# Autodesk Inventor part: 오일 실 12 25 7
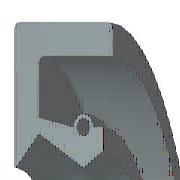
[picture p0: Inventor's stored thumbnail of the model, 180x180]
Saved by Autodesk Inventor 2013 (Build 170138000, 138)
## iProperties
IsCustomPart: 1
Created: 2012-02
Part Number: 오일 실 12 25 7
Material: 고무
Description: 오일-실
Document SubType Name: Modeling
Standard: KS B 2804
Designer: test
Standards Organization: KS
Language: ko-KR
Size Designation: D - 12 25 7
Categories: <MemberInstance><Categories><Category DisplayName="샤프트 부품" InternalName="7f7aeb1f-a693-4053-b835-cee3144e0d98" Mnemonic="SHFT"><Category DisplayName="실링" Intern
Density: 0.93 g/cm^3
Author: test
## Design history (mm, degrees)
revolve "본체" stored, may be unused: angle "d17" = 90 deg
revolve "스프링1" stored, may be unused: angle "d18" = 90 deg
body "Solid1"
sketch "스케치1"
  geometry: L1 (0, 12.5)-(7, 12.5); L2 (7, 10.75)-(1.75, 10.75); L3 (1.75, 7.75)-(4.9, 6); L4 (4.9, 6)-(0, 6); L5 (0, 0)-(9.586, 0) reference; L6 (4.9, 6)-(6.3, 6.875); L7 (0, 18)-(0, -3) reference; L8 (-1.941, 0)-(11.507, 0) reference; L9 (4.2, 8.1)-(1.75, 8.59); L10 (1.75, 8.59)-(1.75, 10.75); L11 (0, 12.5)-(0, 6.088); L12 (4.9, 6)-(0, 6); L13 (1.75, 7.75)-(0.152, 6.028); L14 (7, 12.5)-(7, 10.75); L15 (5.6, 8.1)-(6.3, 8.1); L16 (6.3, 8.1)-(6.3, 6.875); C1 r 0.455 at (4.9, 8.1); A1 r 0.7 centre (4.9, 8.1) between (5.6, 8.1) and (4.2, 8.1); A2 r 0.088 centre (0.088, 6.088) between (0, 6.088) and (0.152, 6.028); 1 further point
  constraints: 28 end point, 5 horizontal alignment, 5 point on line, 4 point on circle, 4 vertical alignment, 3 centre point, 3 tangent, 2 collinear, 2 horizontal, 2 perpendicular, 1 coincident, 1 parallel
  dimensions: "d0" = 25 diameter of L1 L5 (= SD2); "d1" = 1.75 distance of L1.end L2.start (= SD); "d2" = 0.91 diameter of C1 (= SPDI); "d3" = 1.4 diameter of A1 (= SPDA); "d4" = 12 diameter of L3.end L5 (= NND); "d5" = 15.5 diameter of L3.start L5 (= TKDM); "d7" = 17.18 diameter of L9.end L5 (= TKDM + 0.24 x SWDT); "d8" = 1.75 distance between parallel lines of L11 L10 (= SD); "d9" = 4.9 distance from line of L11 C1.centre (= SPDST); "d10" = 16.2 diameter of C1.centre L5 (= HLDM); "d11" = 0.0875 radius of A2 (= 0.25 x LAB); "d12" = 6.3 distance between parallel lines of L11 L16 (= SDI); "d13" = 13.75 diameter of L6.end L5 (= ABDM); "d14" = 7 distance from line of L11 L1.end (= SWDT)
fillet "모깎기1" dims "d6" = 0.3 (= RR)
other parameters: "SD2" = 25 [user parameter; used in 1 equation term], "SWDT" = 7 [user parameter; used in 2 equation terms], "RR" = 0.3 [user parameter; used in 1 equation term], "SD" = 1.75 [user parameter; used in 2 equation terms], "NND" = 12 [user parameter; used in 1 equation term], "SPDA" = 1.4 [user parameter; used in 1 equation term], "SPDI" = 0.91 [user parameter; used in 1 equation term], "TKDM" = 15.5 [user parameter; used in 2 equation terms], "HLDM" = 16.2 [user parameter; used in 1 equation term], "ABDM" = 13.75 [user parameter; used in 1 equation term], "SDI" = 6.3 [user parameter; used in 1 equation term], "SPDST" = 4.9 [user parameter; used in 1 equation term], "LAB" = 0.35 [user parameter; used in 1 equation term], "d15" = 0, "d16" = 0, "d19" = 0
